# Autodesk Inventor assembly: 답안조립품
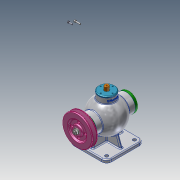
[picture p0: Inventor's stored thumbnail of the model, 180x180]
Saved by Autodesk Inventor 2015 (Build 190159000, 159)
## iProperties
Created: 2025-08
Part Number: 답안조립품
Document SubType Name: Assembly
Designer: user
Author: user
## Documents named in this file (15)
- C:\Users\user\Downloads\750808V1002\답안조립품.iam
- C:\Users\user\Downloads\750808V1002\본체.ipt
- C:\Users\user\Downloads\750808V1002\가져온 구성요소\V-벨트풀리\V-벨트풀리.ipt
- C:\Users\user\Downloads\750808V1002\가져온 구성요소\너트 M8\너트 M8.ipt
- C:\Users\user\Downloads\750808V1002\가져온 구성요소\뒤커버\뒤커버.ipt
- C:\Users\user\Downloads\750808V1002\가져온 구성요소\베어링- 6202\베어링- 6202.ipt
- C:\Users\user\Downloads\750808V1002\가져온 구성요소\볼트 M4 x 12\볼트 M4 x 12.ipt
- C:\Users\user\Downloads\750808V1002\가져온 구성요소\볼트 M4 x 16\볼트 M4 x 16.ipt
- C:\Users\user\Downloads\750808V1002\가져온 구성요소\상부커버\상부커버.ipt
- C:\Users\user\Downloads\750808V1002\가져온 구성요소\슬라이드\슬라이드.ipt
- C:\Users\user\Downloads\750808V1002\가져온 구성요소\앞커버\앞커버.ipt
- C:\Users\user\Downloads\750808V1002\가져온 구성요소\오일실 15 30 7\오일실 15 30 7.ipt
- C:\Users\user\Downloads\750808V1002\가져온 구성요소\칼라\칼라.ipt
- C:\Users\user\Downloads\750808V1002\가져온 구성요소\키 4 x 4 x 12\키 4 x 4 x 12.ipt
- C:\Users\user\Downloads\750808V1002\가져온 구성요소\편심축\편심축.ipt
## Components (1 placed, 1 different names)
1. V-벨트풀리:1
